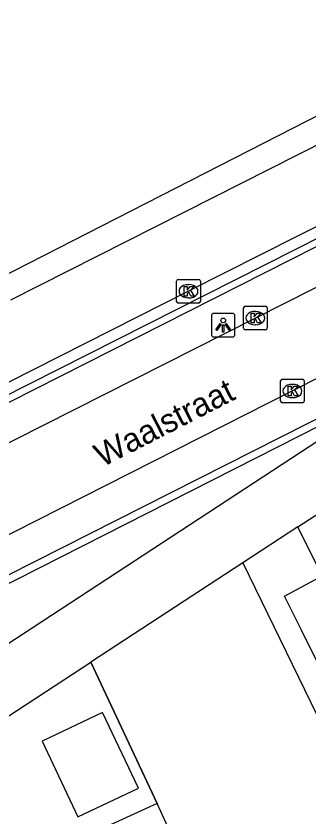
# Model space of a CAD drawing. Extents: x 157321 to 158827, y 386650 to 388532.
# Drawn here: x 157445.32 to 157457.69, y 387562.68 to 387596.54 of the extents above; entities that cross this region are included whole.
import ezdxf

# ---------------------------------------------------------------- set-up
doc = ezdxf.new("R2010")
doc.units = 0
for name, color, linetype in [('IMGEO_Fietspad_gesloten', 7, 'Continuous'), ('IMGEO_Groenvoorziening', 7, 'Continuous'), ('IMGEO_Hek', 7, 'Continuous'), ('IMGEO_Kolk', 7, 'Continuous'), ('IMGEO_Lichtpunt', 7, 'Continuous'), ('IMGEO_Meer_plas_ven_vijver', 7, 'Continuous'), ('IMGEO_Muur', 7, 'Continuous'), ('IMGEO_Openbare_ruimte_label', 7, 'Continuous'), ('IMGEO_Pand', 7, 'Continuous'), ('IMGEO_Rijbaan_lokaal_open', 7, 'Continuous'), ('IMGEO_Voetpad_open', 7, 'Continuous')]:
    doc.layers.add(name, color=color, linetype=linetype)

msp = doc.modelspace()

# ---------------------------------------------------------------- linework, layer by layer
at = {"layer": 'IMGEO_Fietspad_gesloten'}
for points in [[(157416.027, 387563.82), (157433.825, 387572.851), (157455.422, 387583.768), (157471.557, 387591.939)], [(157473.14, 387588.869), (157456.986, 387580.686), (157435.385, 387569.732), (157418.265, 387561.069)]]:
    msp.add_lwpolyline(points, dxfattribs=at)
at = {"layer": 'IMGEO_Groenvoorziening'}
for points in [[(157458.246, 387572.872), (157457.215, 387574.942)], [(157454.897, 387573.424), (157468.179, 387546.099), (157455.611, 387539.998), (157450.114, 387543.452)], [(157448.47, 387569.217), (157451.273, 387563.255)]]:
    msp.add_lwpolyline(points, dxfattribs=at)
at = {"layer": 'IMGEO_Hek'}
msp.add_lwpolyline([(157451.273, 387563.255), (157448.47, 387569.217)], dxfattribs=at)
at = {"layer": 'IMGEO_Kolk'}
for p, q in [((157452.099, 387584.475), (157452.099, 387585.327)), ((157452.174, 387585.401), (157453.026, 387585.401)), ((157452.587, 387585.181), (157452.612, 387585.181)), ((157453.1, 387585.327), (157453.1, 387584.475)), ((157452.61, 387584.621), (157452.585, 387584.621)), ((157453.026, 387584.401), (157452.174, 387584.401)), ((157454.924, 387583.343), (157454.924, 387584.195)), ((157454.999, 387584.269), (157455.851, 387584.269)), ((157455.925, 387584.195), (157455.925, 387583.343)), ((157455.412, 387584.049), (157455.437, 387584.049)), ((157455.435, 387583.489), (157455.41, 387583.489)), ((157455.851, 387583.269), (157454.999, 387583.269)), ((157456.49, 387580.259), (157456.49, 387581.111)), ((157456.565, 387581.185), (157457.417, 387581.185)), ((157457.491, 387581.111), (157457.491, 387580.259)), ((157456.978, 387580.965), (157457.003, 387580.965)), ((157457.001, 387580.405), (157456.976, 387580.405)), ((157457.417, 387580.185), (157456.565, 387580.185))]:
    msp.add_line(p, q, dxfattribs=at)
for points in [[(157452.099, 387584.475), (157452.099, 387585.327)], [(157452.174, 387585.401), (157453.026, 387585.401)], [(157453.1, 387585.327), (157453.1, 387584.475)], [(157452.42, 387585.101), (157452.543, 387585.101), (157452.543, 387584.95), (157452.673, 387585.101), (157452.837, 387585.101), (157452.691, 387584.95), (157452.844, 387584.701), (157452.692, 387584.701), (157452.607, 387584.865), (157452.543, 387584.798), (157452.543, 387584.701), (157452.42, 387584.701), (157452.42, 387585.101)], [(157453.026, 387584.401), (157452.174, 387584.401)], [(157454.924, 387583.343), (157454.924, 387584.195)], [(157454.999, 387584.269), (157455.851, 387584.269)], [(157455.925, 387584.195), (157455.925, 387583.343)], [(157455.245, 387583.969), (157455.368, 387583.969), (157455.368, 387583.818), (157455.498, 387583.969), (157455.662, 387583.969), (157455.516, 387583.818), (157455.669, 387583.569), (157455.517, 387583.569), (157455.432, 387583.733), (157455.368, 387583.666), (157455.368, 387583.569), (157455.245, 387583.569), (157455.245, 387583.969)], [(157455.851, 387583.269), (157454.999, 387583.269)], [(157456.49, 387580.259), (157456.49, 387581.111)], [(157456.565, 387581.185), (157457.417, 387581.185)], [(157457.491, 387581.111), (157457.491, 387580.259)], [(157456.811, 387580.885), (157456.934, 387580.885), (157456.934, 387580.734), (157457.064, 387580.885), (157457.228, 387580.885), (157457.082, 387580.734), (157457.235, 387580.485), (157457.083, 387580.485), (157456.998, 387580.649), (157456.934, 387580.582), (157456.934, 387580.485), (157456.811, 387580.485), (157456.811, 387580.885)], [(157457.417, 387580.185), (157456.565, 387580.185)]]:
    msp.add_lwpolyline(points, dxfattribs=at)
for centre, start, end in [((157452.176, 387585.325), 91.552, 178.448), ((157452.176, 387585.325), 91.552, 178.448), ((157453.024, 387585.325), 1.552, 88.448), ((157453.024, 387585.325), 1.552, 88.448), ((157452.176, 387584.477), 181.552, 268.448), ((157452.176, 387584.477), 181.552, 268.448), ((157453.024, 387584.477), 271.552, 358.448), ((157453.024, 387584.477), 271.552, 358.448), ((157455.001, 387584.193), 91.552, 178.448), ((157455.001, 387584.193), 91.552, 178.448), ((157455.849, 387584.193), 1.552, 88.448), ((157455.849, 387584.193), 1.552, 88.448), ((157455.001, 387583.345), 181.552, 268.448), ((157455.001, 387583.345), 181.552, 268.448), ((157455.849, 387583.345), 271.552, 358.448), ((157455.849, 387583.345), 271.552, 358.448), ((157456.567, 387581.109), 91.552, 178.448), ((157456.567, 387581.109), 91.552, 178.448), ((157457.415, 387581.109), 1.552, 88.448), ((157457.415, 387581.109), 1.552, 88.448), ((157456.567, 387580.261), 181.552, 268.448), ((157456.567, 387580.261), 181.552, 268.448), ((157457.415, 387580.261), 271.552, 358.448), ((157457.415, 387580.261), 271.552, 358.448)]:
    msp.add_arc(centre, 0.0765, start, end, dxfattribs=at)
for centre, major_axis, ratio, start_param, end_param in [((157452.586, 387584.901), (-0.387, 0.002), 0.722429, 4.712389, 7.853982), ((157452.611, 387584.901), (-0.39, 0.002), 0.717154, 1.570796, 4.712389), ((157455.411, 387583.769), (-0.387, 0.002), 0.722429, 4.712389, 7.853982), ((157455.436, 387583.769), (-0.39, 0.002), 0.717154, 1.570796, 4.712389), ((157456.977, 387580.685), (-0.387, 0.002), 0.722429, 4.712389, 7.853982), ((157457.002, 387580.685), (-0.39, 0.002), 0.717154, 1.570796, 4.712389)]:
    msp.add_ellipse(centre, major_axis=major_axis, ratio=ratio, start_param=start_param, end_param=end_param, dxfattribs=at)
at = {"layer": 'IMGEO_Lichtpunt'}
for p, q in [((157453.566, 387583.873), (157453.566, 387583.066)), ((157453.566, 387583.873), (157453.566, 387583.066)), ((157454.468, 387583.968), (157453.66, 387583.968)), ((157454.468, 387583.968), (157453.66, 387583.968)), ((157454.562, 387583.066), (157454.562, 387583.873)), ((157454.562, 387583.066), (157454.562, 387583.873)), ((157453.66, 387582.972), (157454.468, 387582.972)), ((157453.66, 387582.972), (157454.468, 387582.972))]:
    msp.add_line(p, q, dxfattribs=at)
for points in [[(157453.94, 387583.537), (157453.979, 387583.509), (157453.791, 387583.247), (157453.753, 387583.274), (157453.94, 387583.537)], [(157454.042, 387583.489), (157454.089, 387583.489), (157454.089, 387583.167), (157454.042, 387583.167), (157454.042, 387583.489)], [(157454.152, 387583.509), (157454.19, 387583.536), (157454.377, 387583.274), (157454.338, 387583.246), (157454.152, 387583.509)]]:
    msp.add_lwpolyline(points, dxfattribs=at)
msp.add_circle((157454.065, 387583.671), 0.0994, dxfattribs=at)
for centre, start, end in [((157453.66, 387583.873), 90, 180), ((157453.66, 387583.873), 90, 180), ((157454.468, 387583.873), 0, 90), ((157454.468, 387583.873), 0, 90), ((157453.66, 387583.066), 180, 270), ((157453.66, 387583.066), 180, 270), ((157454.468, 387583.066), 270, 0), ((157454.468, 387583.066), 270, 360)]:
    msp.add_arc(centre, 0.0946, start, end, dxfattribs=at)
at = {"layer": 'IMGEO_Meer_plas_ven_vijver'}
msp.add_lwpolyline([(157473.392, 387543.678), (157470.495, 387543.879), (157463.702, 387557.826), (157463.092, 387559.076), (157457.38, 387570.552), (157456.654, 387572.01), (157458.246, 387572.872)], dxfattribs=at)
at = {"layer": 'IMGEO_Muur'}
for points in [[(157429.806, 387573.314), (157438.415, 387577.215), (157470.771, 387593.59)], [(157470.913, 387593.326), (157438.555, 387576.929)], [(157441.48, 387571.141), (157473.819, 387587.515)], [(157459.097, 387579.703), (157441.648, 387570.849), (157420.115, 387558.795)]]:
    msp.add_lwpolyline(points, dxfattribs=at)
at = {"layer": 'IMGEO_Pand'}
for points in [[(157450.489, 387563.891), (157448.973, 387567.1), (157446.413, 387565.891), (157447.928, 387562.682), (157450.489, 387563.891)], [(157451.273, 387563.255), (157445.544, 387560.633), (157452.333, 387545.796)], [(157458.143, 387548.24), (157451.273, 387563.255)]]:
    msp.add_lwpolyline(points, dxfattribs=at)
at = {"layer": 'IMGEO_Rijbaan_lokaal_open'}
for points in [[(157466.982, 387595.618), (157445.088, 387584.519)], [(157468.366, 387592.876), (157467.91, 387592.639), (157452.596, 387584.902), (157438.44, 387577.734), (157438.25, 387577.629), (157429.654, 387573.707)], [(157434.731, 387549.184), (157431.648, 387555.145), (157429.276, 387559.732), (157458.882, 387579.113), (157459.1, 387579.229), (157459.289, 387579.324)], [(157457.215, 387574.942), (157458.887, 387576.036)], [(157457.215, 387574.942), (157454.897, 387573.424)], [(157454.897, 387573.424), (157448.47, 387569.217)], [(157434.202, 387559.877), (157448.47, 387569.217)]]:
    msp.add_lwpolyline(points, dxfattribs=at)
at = {"layer": 'IMGEO_Voetpad_open'}
msp.add_lwpolyline([(157444.6, 387585.462), (157468.188, 387597.53)], dxfattribs=at)

# ---------------------------------------------------------------- texts
at = {"layer": 'IMGEO_Openbare_ruimte_label'}
msp.add_text('Waalstraat', height=1, rotation=27.1288, dxfattribs=at).set_placement((157448.957, 387577.45))

doc.saveas('drawing.dxf')
